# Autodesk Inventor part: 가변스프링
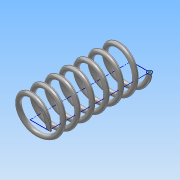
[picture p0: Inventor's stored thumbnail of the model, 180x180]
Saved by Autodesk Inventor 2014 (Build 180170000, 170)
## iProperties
Created: 2018-11
Part Number: 가변스프링
Material: 강철, 탄소
Document SubType Name: Modeling
Designer: 703
Density: 7.87 g/cm^3
Appearance: 반연마
Mass: 8.61391 g
Surface Area: 22.1525 cm^2
Volume: 1.09453 cm^3
Author: 703
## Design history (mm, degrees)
sketch "스케치1"
  geometry: L1 (0, 0)-(-8, 0); L2 (-8, 0)-(-8, -43.5); L3 (-8, -43.5)-(0, -43.5); L4 (0, -43.5)-(0, 0); C1 r 1 at (0, 0); 1 further point
  constraints: 8 end point, 2 parallel, 1 centre point, 1 coincident, 1 horizontal, 1 perpendicular
  dimensions: "d0" = 2 diameter of C1; "d1" = 43.5 distance of L1.end L2.end (derived); "d2" = 16 diameter of point (0, 0) L2
feature "코일1" pitch "d3" = 10; turns "d5" = 7; dims "d4" = 43.5 (= d1), "d6" = 0, angle "d7" = 90 deg, angle "d8" = 90 deg, "d9" = 0, "d10" = 0
sketch "스케치2"
  geometry: C1 r 25 at (0, 0); 1 further point
  constraints: 1 centre point, 1 coincident
  dimensions: "d11" = 50 diameter of C1
extrude "돌출1" cut sketch "스케치2" distance "d12" = 10; taper "d13" = 0 deg
node "작업 평면1"
sketch "스케치3"
  geometry: C1 r 25 at (8, 0); 1 further point
  constraints: 1 centre point, 1 coincident
  dimensions: "d14" = 50 diameter of C1
extrude "돌출2" cut sketch "스케치3" distance "d15" = 10; taper "d16" = 0 deg
node "솔리드1"
